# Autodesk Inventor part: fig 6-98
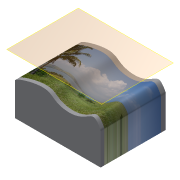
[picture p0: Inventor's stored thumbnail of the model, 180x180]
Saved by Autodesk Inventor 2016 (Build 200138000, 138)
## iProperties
Created: 2012-07
Part Number: fig 6-98
Material: Generic
Document SubType Name: Modeling
Designer: CADCIM
Density: 1 g/cm^3
Appearance: Default
Author: CADCIM
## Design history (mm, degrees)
sketch "Sketch1"
  geometry: L1 (0, 0)-(0, 12.146); L2 (32.23, 12.146)-(32.23, 0); L3 (32.23, 0)-(0, 0); 5 further points
  constraints: 6 end point, 1 parallel, 1 perpendicular, 1 vertical, 7 other
extrude "Extrusion1" new body sketch "Sketch1" distance "d0" = 24.5; taper "d1" = 0 deg
workplane "Work Plane1"
fillet "Fillet1" dims "d19" = 2
sketch "Sketch2"
  geometry: L1 (-33.343, 22.666)-(0.669, 22.666); L2 (0.669, 22.666)-(0.669, 1.409); L3 (0.669, 1.409)-(-33.343, 1.409); L4 (-33.343, 1.409)-(-33.343, 22.666); 1 other entity
  constraints: 2 other
feature "Decal1" sketch "Sketch2"
body "Solid1"
node "Image1"
other parameters: "d2" = 22
